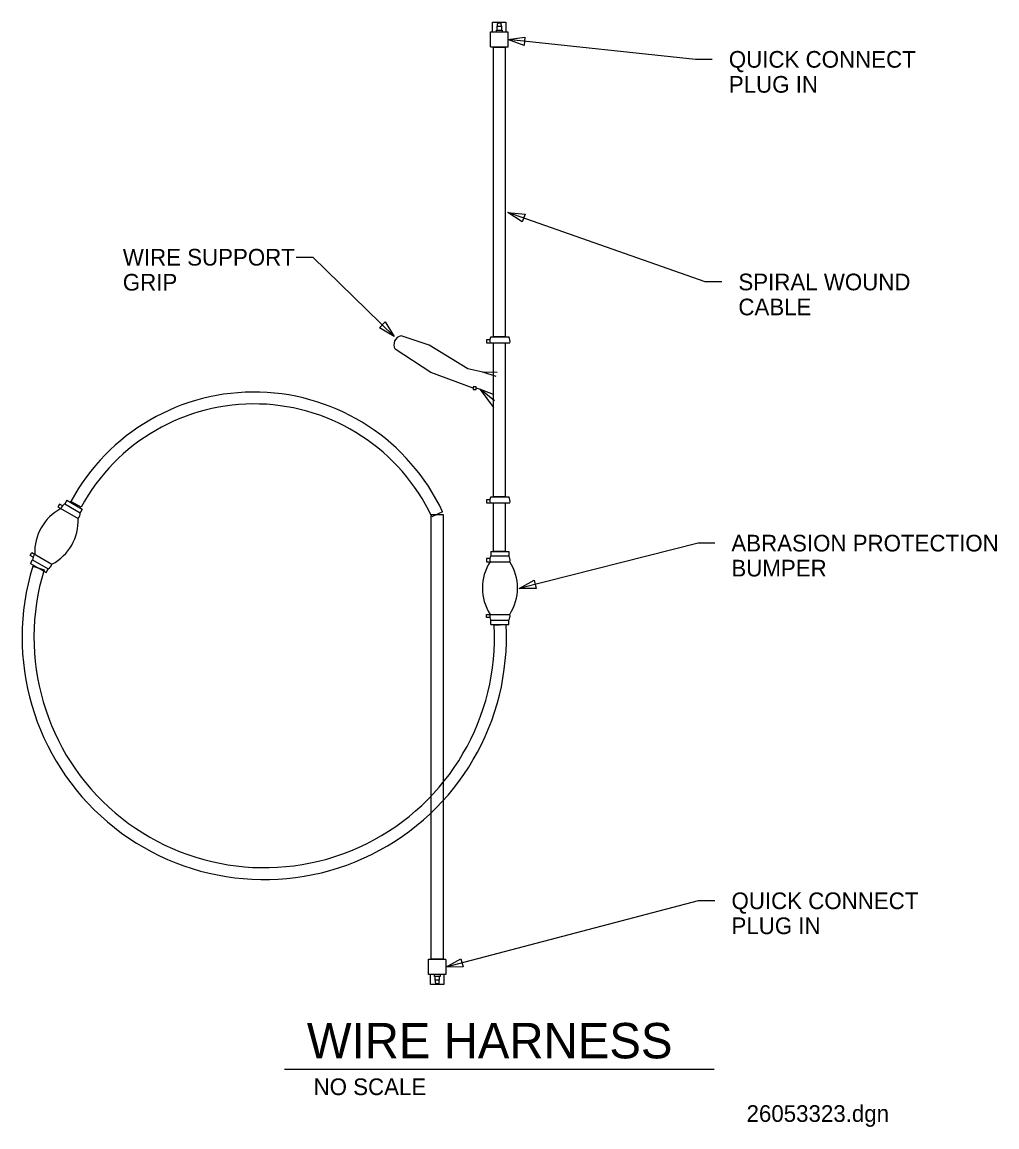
# Model space of a CAD drawing. Extents: x 10326.4 to 10365.4, y 10067.5 to 10111.7.
import ezdxf

# ---------------------------------------------------------------- set-up
doc = ezdxf.new("R2010")
doc.units = 0
for name, color, linetype in [('Level 3', 7, 'Continuous'), ('Level 52', 7, 'Continuous'), ('Level 60', 7, 'Continuous'), ('Level 61', 7, 'Continuous'), ('Level 63', 7, 'Continuous')]:
    doc.layers.add(name, color=color, linetype=linetype)

msp = doc.modelspace()

# ---------------------------------------------------------------- linework, layer by layer
at = {"layer": 'Level 52'}
msp.add_line((10336.923, 10069.793), (10354.113, 10069.793), dxfattribs=at)
at = {"layer": 'Level 60'}
msp.add_lwpolyline([(10345.756, 10092.442), (10345.756, 10090.496), (10345.281, 10090.496), (10345.281, 10092.442)], close=True, dxfattribs=at)
at = {"layer": 'Level 61'}
for p, q in [((10345.252, 10111.67), (10345.784, 10111.67)), ((10345.252, 10111.278), (10345.252, 10111.67)), ((10345.458, 10111.643), (10345.578, 10111.643)), ((10345.784, 10111.67), (10345.784, 10111.278)), ((10345.173, 10111.278), (10345.863, 10111.278)), ((10345.173, 10110.683), (10345.173, 10111.278)), ((10345.406, 10111.354), (10345.63, 10111.354)), ((10345.406, 10111.278), (10345.406, 10111.354)), ((10345.434, 10111.354), (10345.434, 10111.501)), ((10345.434, 10111.501), (10345.602, 10111.501)), ((10345.602, 10111.501), (10345.602, 10111.354)), ((10345.63, 10111.354), (10345.63, 10111.278)), ((10345.863, 10111.278), (10345.863, 10110.667)), ((10345.863, 10110.667), (10345.173, 10110.667)), ((10342.719, 10098.743), (10341.591, 10099.119)), ((10345.01, 10098.964), (10345.01, 10098.839)), ((10345.145, 10098.964), (10345.01, 10098.964)), ((10345.01, 10098.839), (10345.939, 10098.839)), ((10345.186, 10099.077), (10345.904, 10099.077)), ((10342.785, 10097.656), (10341.354, 10098.591)), ((10344.26, 10097.803), (10342.719, 10098.743)), ((10344.479, 10097.032), (10342.785, 10097.656)), ((10344.861, 10097.671), (10344.26, 10097.803)), ((10345.438, 10097.653), (10344.836, 10097.672)), ((10345.4, 10097.503), (10344.861, 10097.671)), ((10344.592, 10097.089), (10344.479, 10097.089)), ((10344.479, 10097.089), (10344.479, 10096.976)), ((10344.592, 10096.976), (10344.592, 10097.089)), ((10344.479, 10096.976), (10344.592, 10096.976)), ((10344.767, 10096.974), (10344.592, 10097.032)), ((10345.293, 10096.779), (10344.761, 10096.976)), ((10345.325, 10096.525), (10344.761, 10096.976)), ((10345.306, 10096.261), (10344.767, 10096.974)), ((10345.186, 10092.68), (10345.904, 10092.68)), ((10327.918, 10092.39), (10327.856, 10092.282)), ((10327.856, 10092.282), (10328.662, 10091.821)), ((10328.035, 10092.323), (10327.918, 10092.39)), ((10328.21, 10092.546), (10328.127, 10092.4)), ((10328.127, 10092.4), (10328.75, 10092.044)), ((10328.21, 10092.546), (10328.833, 10092.19)), ((10328.79, 10092.268), (10328.372, 10092.494)), ((10328.833, 10092.19), (10328.75, 10092.044)), ((10345.145, 10092.567), (10345.01, 10092.567)), ((10345.01, 10092.567), (10345.01, 10092.442)), ((10345.01, 10092.442), (10345.939, 10092.442)), ((10343.25, 10092.085), (10342.82, 10091.883)), ((10326.749, 10090.344), (10326.811, 10090.453)), ((10326.811, 10090.453), (10327.617, 10089.992)), ((10345.186, 10090.496), (10345.186, 10090.328)), ((10345.186, 10090.496), (10345.904, 10090.496)), ((10345.904, 10090.496), (10345.904, 10090.328)), ((10326.866, 10090.277), (10326.749, 10090.344)), ((10326.762, 10090.014), (10326.846, 10090.159)), ((10326.762, 10090.014), (10327.386, 10089.657)), ((10326.846, 10090.159), (10327.469, 10089.803)), ((10345.01, 10090.216), (10345.01, 10090.091)), ((10345.145, 10090.216), (10345.01, 10090.216)), ((10345.01, 10090.091), (10345.939, 10090.091)), ((10345.186, 10090.328), (10345.904, 10090.328)), ((10326.847, 10089.905), (10327.301, 10089.766)), ((10327.386, 10089.657), (10327.469, 10089.803)), ((10345.01, 10087.984), (10345.939, 10087.984)), ((10345.01, 10087.859), (10345.01, 10087.984)), ((10345.145, 10087.859), (10345.01, 10087.859)), ((10345.186, 10087.579), (10345.186, 10087.746)), ((10345.186, 10087.746), (10345.904, 10087.746)), ((10345.186, 10087.579), (10345.904, 10087.579)), ((10345.317, 10087.548), (10345.791, 10087.573)), ((10345.904, 10087.579), (10345.904, 10087.746)), ((10342.69, 10073.578), (10342.69, 10074.189)), ((10342.69, 10074.189), (10343.38, 10074.189)), ((10343.38, 10074.174), (10343.38, 10073.578)), ((10343.38, 10073.578), (10342.69, 10073.578)), ((10342.769, 10073.186), (10342.769, 10073.578)), ((10342.923, 10073.502), (10342.923, 10073.578)), ((10343.147, 10073.502), (10342.923, 10073.502)), ((10342.951, 10073.356), (10342.951, 10073.502)), ((10343.119, 10073.356), (10342.951, 10073.356)), ((10343.095, 10073.214), (10342.975, 10073.214)), ((10343.119, 10073.502), (10343.119, 10073.356)), ((10343.147, 10073.578), (10343.147, 10073.502)), ((10343.301, 10073.578), (10343.301, 10073.186)), ((10343.301, 10073.186), (10342.769, 10073.186))]:
    msp.add_line(p, q, dxfattribs=at)
for points in [[(10345.756, 10110.667), (10345.756, 10099.077), (10345.281, 10099.077), (10345.281, 10110.667)], [(10345.756, 10098.839), (10345.756, 10092.68), (10345.281, 10092.68), (10345.281, 10098.839)], [(10342.798, 10074.189), (10342.798, 10091.984), (10343.273, 10091.984), (10343.273, 10074.189)]]:
    msp.add_lwpolyline(points, close=True, dxfattribs=at)
for centre, radius, start, end in [((10345.738, 10111.521), 0.305, 156.5565, 183.8946), ((10345.298, 10111.521), 0.305, 356.1054, 23.4435), ((10341.649, 10098.776), 0.348, 99.5873, 212.1703), ((10345.453, 10098.916), 0.312, 148.9846, 194.2493), ((10345.637, 10098.916), 0.312, 345.7507, 31.0154), ((10335.708, 10088.54), 8.334, 25.1722, 151.6779), ((10335.708, 10088.54), 7.859, 25.1722, 151.6779), ((10345.453, 10092.519), 0.312, 148.9846, 194.2493), ((10345.637, 10092.519), 0.312, 345.7507, 31.0154), ((10328.879, 10090.484), 1.948, 117.5187, 182.9771), ((10328.279, 10092.128), 0.312, 119.2325, 164.4972), ((10326.717, 10091.719), 1.948, 297.5187, 2.9771), ((10328.438, 10092.037), 0.312, 315.9986, 1.2633), ((10327.157, 10090.166), 0.312, 135.9986, 181.2633), ((10327.316, 10090.075), 0.312, 299.2325, 344.4972), ((10346.79, 10089.037), 1.948, 147.2708, 212.7292), ((10345.453, 10090.167), 0.312, 148.9846, 194.2493), ((10345.637, 10090.167), 0.312, 345.7507, 31.0154), ((10344.3, 10089.037), 1.948, 327.2708, 32.7292), ((10336.114, 10087.07), 9.691, 162.9877, 2.9771), ((10336.114, 10087.07), 9.216, 162.9877, 2.9771), ((10345.453, 10087.907), 0.312, 165.7507, 211.0154), ((10345.637, 10087.907), 0.312, 328.9846, 14.2493), ((10343.255, 10073.335), 0.305, 176.1054, 203.4435), ((10342.815, 10073.335), 0.305, 336.5565, 3.8946)]:
    msp.add_arc(centre, radius, start, end, dxfattribs=at)
at = {"layer": 'Level 63'}
for p, q in [((10353.371, 10110.18), (10345.863, 10110.973)), ((10354.038, 10110.18), (10353.371, 10110.18)), ((10353.753, 10101.277), (10345.865, 10104.055)), ((10337.386, 10102.266), (10338.052, 10102.266)), ((10338.052, 10102.266), (10341.319, 10099.093)), ((10354.42, 10101.277), (10353.753, 10101.277)), ((10353.473, 10090.832), (10346.314, 10089.021)), ((10354.139, 10090.832), (10353.473, 10090.832)), ((10353.478, 10076.528), (10343.38, 10073.876)), ((10354.145, 10076.528), (10353.478, 10076.528))]:
    msp.add_line(p, q, dxfattribs=at)
for points in [[(10346.508, 10110.737), (10345.863, 10110.973), (10346.543, 10111.068)], [(10346.438, 10103.676), (10345.865, 10104.055), (10346.549, 10103.99)], [(10340.957, 10099.677), (10341.319, 10099.093), (10340.725, 10099.438)], [(10347.001, 10089.023), (10346.314, 10089.021), (10346.919, 10089.346)], [(10344.067, 10073.884), (10343.38, 10073.876), (10343.982, 10074.206)]]:
    msp.add_lwpolyline(points, close=True, dxfattribs=at)

# ---------------------------------------------------------------- texts
at = {"layer": 'Level 3'}
msp.add_text('26053323.dgn', height=0.66667, dxfattribs=at).set_placement((10355.414, 10067.687))
at = {"layer": 'Level 52'}
for s, height, p in [('WIRE HARNESS', 1.41667, (10337.819, 10070.226)), ('NO SCALE', 0.6667, (10338.087, 10068.758))]:
    msp.add_text(s, height=height, dxfattribs=at).set_placement(p)
at = {"layer": 'Level 63'}
for s, height, p in [('QUICK CONNECT', 0.66667, (10354.705, 10109.847)), ('PLUG IN', 0.6667, (10354.705, 10108.847)), ('WIRE SUPPORT', 0.66667, (10330.454, 10101.933)), ('GRIP', 0.6667, (10330.454, 10100.933)), ('SPIRAL WOUND', 0.66667, (10355.087, 10100.944)), ('CABLE', 0.6667, (10355.087, 10099.944)), ('ABRASION PROTECTION', 0.66667, (10354.806, 10090.499)), ('BUMPER', 0.6667, (10354.806, 10089.499)), ('QUICK CONNECT', 0.66667, (10354.811, 10076.195)), ('PLUG IN', 0.6667, (10354.811, 10075.195))]:
    msp.add_text(s, height=height, dxfattribs=at).set_placement(p)

doc.saveas('drawing.dxf')
